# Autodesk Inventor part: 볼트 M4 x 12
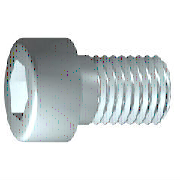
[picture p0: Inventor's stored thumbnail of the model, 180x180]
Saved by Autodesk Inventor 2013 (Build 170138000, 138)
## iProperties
IsCustomPart: 1
Created: 2012-02
Part Number: 볼트 M4 x 12
Material: 강철, 연강
Description: 원통형 머리 캡 나사
Document SubType Name: Modeling
Standard: JIS B 1176
Designer: mdu-01
Standards Organization: JIS
Language: ko-KR
Size Designation: M4 x 12
Categories: <MemberInstance><Categories><Category DisplayName="조임쇠" InternalName="e4da775c-781d-43d5-af7c-5136215cf5a6" Mnemonic="FSTN"><Category DisplayName="볼트" InternalN
Density: 1 g/cm^3
Author: mdu-01
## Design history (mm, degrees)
sketch "스케치1"
  geometry: L1 (-1, 0)-(12, 0); L2 (12, 0)-(12, 2); L3 (12, 2)-(1.75, 2); L4 (1.75, 2)-(1.32, 2); L5 (1.32, 2)-(0, 2); L6 (0, 2)-(0, 3.5); L7 (0, 3.5)-(-4, 3.5); L8 (-4, 3.5)-(-4, 1.732); L9 (-4, 1.732)-(-2, 1.732); L10 (-2, 1.732)-(-1, 0); L11 (-7.2, 0)-(15.2, 0) reference; L12 (0, -0.7)-(0, 4.2) reference; L13 (1.75, 2)-(0, 2)
  constraints: 22 end point, 6 parallel, 2 collinear, 2 perpendicular, 1 horizontal, 1 point on line
  dimensions: "d1" = 10.25 distance from line of L3.end L2 (= GEL); "d2" = 0.42952 distance of L4.end L3.end (computed from GAL); "d3" = 4 distance between parallel lines of L8 L6 (= KOH); "d4" = 2 distance of L8.end L9.end (= INTI); "d5" = 60 deg angle of L10 L1; "d6" = 4 diameter of L3 L1 (= GD); "d7" = 4 diameter of L5 L1 (= BDM); "d8" = 3.4641 diameter of L9 L1 (= 1.1547 x SW); "d9" = 7 diameter of L7 L1 (= KOD); "d26" = 12 distance between parallel lines of L12 L2 (= NLG)
revolve "본체" sketch "스케치1" stored, may be unused: angle "d10" = 90 deg
sketch "스케치2"
  geometry: L1 (0, -4.9)-(0, 4.9) reference; L2 (-4.9, 0)-(4.9, 0) reference; L3 (1.732, 0)-(0.866, -1.5); L4 (0.866, -1.5)-(-0.866, -1.5); L5 (-0.866, -1.5)-(-1.732, 0); L6 (-1.732, 0)-(-0.866, 1.5); L7 (-0.866, 1.5)-(0.866, 1.5); L8 (0.866, 1.5)-(1.732, 0); 2 further points
  constraints: 12 end point, 1 coincident, 1 horizontal alignment, 1 point on line, 12 other
extrude "슬롯" join sketch "스케치2" stored distance "d11" = 10; taper "d12" = 0 deg
workplane "Work Plane1"
fillet "Fillet2" dims "d30" = 0.1 (= R)
body "Solid1"
fillet "모깎기1" dims "d17" = 0.4 (= RR)
feature "스레드" dims "d13" = 10.25 (= GEL), "d14" = 0
chamfer "모따기1" distance "d15" = 0.42941 (= -0.5 x SPD + 0.5 x GD); stored, may be unused: second distance "d16" = 0.42941 (= GUL), angle "d27" = 45 deg
other parameters: "GD" = 4 (= NND) [user parameter; used in 2 equation terms], "NLG" = 12 [user parameter; used in 1 equation term], "GEL" = 10.25 [user parameter; used in 2 equation terms], "KOD" = 7 [user parameter; used in 1 equation term], "KOH" = 4 [user parameter; used in 1 equation term], "INTI" = 2 [user parameter; used in 1 equation term], "GAL" = 0.42941 (= 0.61345 x PTC) [user parameter; used in 1 equation term], "GUL" = 0.42941 (= 0.61345 x PTC) [user parameter; used in 1 equation term], "BDM" = 4 (= NND) [user parameter; used in 1 equation term], "SW" = 3 [user parameter; used in 2 equation terms], "RR" = 0.4 [user parameter; used in 1 equation term], "SPD" = 3.14117 (= NND - 1.2269 x PTC) [user parameter; used in 1 equation term], "d19" = 0, "d28" = 0, "d29" = 0, "R" = 0.1 [user parameter; used in 1 equation term], "PHH" = 0.2 [user parameter], "GD1" = 3.14117 (= THREADDIA - 1.2269 x PTC) [user parameter], "THREADDIA" = 4 [user parameter; used in 1 equation term], "FAWI" = 45 deg [user parameter], "TPU" = 14.28571 (computed from PTC) [user parameter], "PTC" = 0.7 [user parameter; used in 5 equation terms], "NND" = 4 [user parameter; used in 3 equation terms], "TOA" = 30 deg [user parameter], "E0" = 3.465 (= 1.155 x SW) [user parameter]
